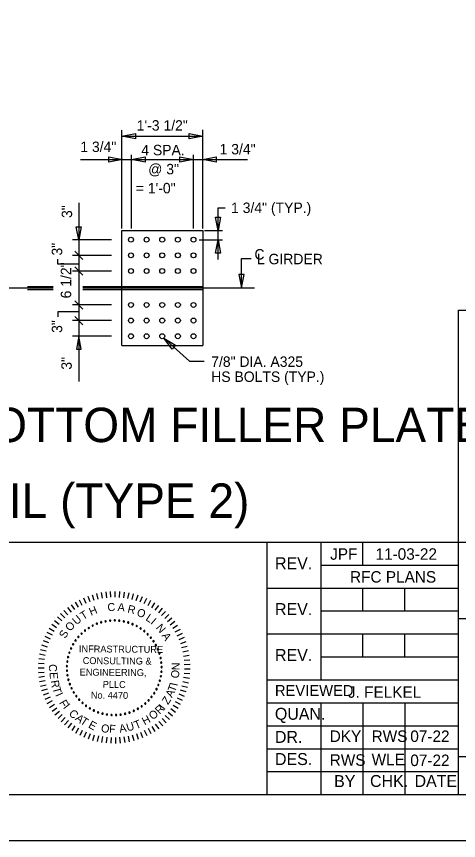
# Model space of a CAD drawing. Extents: x 1970675.2 to 1970715, y 796143 to 796167.2.
# Drawn here: x 1970703.03 to 1970708.33, y 796143.05 to 796152.92 of the extents above; entities that cross this region are included whole.
import ezdxf

# ---------------------------------------------------------------- set-up
doc = ezdxf.new("R2010")
doc.units = 0
for name, color, linetype in [('BR_AUTO DIMENSION', 7, 'Continuous'), ('BR_BORDER LINES', 7, 'Continuous'), ('BR_CENTER LINES', 7, 'Continuous'), ('BR_STRUCTURAL STEEL', 7, 'Continuous'), ('BR_TEXT', 7, 'Continuous'), ('Level 31', 7, 'Continuous')]:
    doc.layers.add(name, color=color, linetype=linetype)

msp = doc.modelspace()

# ---------------------------------------------------------------- linework, layer by layer
at = {"layer": 'BR_AUTO DIMENSION'}
for p, q in [((1970704.2931, 796150.3805), (1970704.2931, 796151.5573)), ((1970705.2619, 796150.3805), (1970705.2619, 796151.5617)), ((1970704.2931, 796151.4842), (1970705.2619, 796151.4842)), ((1970704.4103, 796150.3805), (1970704.4103, 796151.2604)), ((1970705.1525, 796150.3805), (1970705.1525, 796151.2604)), ((1970703.7969, 796151.2042), (1970705.7973, 796151.2042)), ((1970703.7781, 796150.686), (1970703.7781, 796148.5449)), ((1970705.4457, 796150.0076), (1970705.4457, 796150.6251)), ((1970705.4457, 796150.6251), (1970705.5332, 796150.6251)), ((1970705.2845, 796150.3537), (1970705.5013, 796150.3537)), ((1970704.171, 796150.2444), (1970703.7024, 796150.2444)), ((1970705.2194, 796150.2444), (1970705.5013, 796150.2444)), ((1970703.8279, 796150.0063), (1970703.7284, 796150.1074)), ((1970704.171, 796150.0569), (1970703.7024, 796150.0569)), ((1970705.7275, 796150.0186), (1970705.8434, 796150.0186)), ((1970705.7275, 796149.6662), (1970705.7275, 796150.0186)), ((1970704.171, 796149.8694), (1970703.7024, 796149.8694)), ((1970703.8279, 796149.8188), (1970703.7284, 796149.9199)), ((1970703.8279, 796149.4126), (1970703.7284, 796149.5137)), ((1970704.171, 796149.4631), (1970703.7024, 796149.4631)), ((1970704.171, 796149.2756), (1970703.7024, 796149.2756)), ((1970703.8279, 796149.2251), (1970703.7284, 796149.3262)), ((1970704.171, 796149.0881), (1970703.7024, 796149.0881)), ((1970705.1039, 796148.7898), (1970704.7961, 796149.0655)), ((1970705.1039, 796148.7898), (1970705.2808, 796148.7898))]:
    msp.add_line(p, q, dxfattribs=at)
for points in [[(1970704.4556, 796151.453), (1970704.2931, 796151.4842), (1970704.4556, 796151.5155)], [(1970705.0994, 796151.5155), (1970705.2619, 796151.4842), (1970705.0994, 796151.453)], [(1970704.1384, 796151.2354), (1970704.3009, 796151.2042), (1970704.1384, 796151.1729)], [(1970704.5728, 796151.1729), (1970704.4103, 796151.2042), (1970704.5728, 796151.2354)], [(1970704.99, 796151.2354), (1970705.1525, 796151.2042), (1970704.99, 796151.1729)], [(1970705.4244, 796151.1729), (1970705.2619, 796151.2042), (1970705.4244, 796151.2354)], [(1970705.4769, 796150.5162), (1970705.4457, 796150.3537), (1970705.4144, 796150.5162)], [(1970703.8081, 796150.4004), (1970703.7781, 796150.2444), (1970703.7481, 796150.4004)], [(1970705.4144, 796150.0819), (1970705.4457, 796150.2444), (1970705.4769, 796150.0819)], [(1970705.6962, 796149.8287), (1970705.7275, 796149.6662), (1970705.7587, 796149.8287)], [(1970703.7521, 796148.9318), (1970703.8042, 796148.9318), (1970703.7781, 796149.0881)], [(1970704.8963, 796148.9338), (1970704.7961, 796149.0655), (1970704.938, 796148.9803)]]:
    msp.add_lwpolyline(points, close=True, dxfattribs=at)
for points in [[(1970703.7781, 796149.9508), (1970703.5252, 796149.9508), (1970703.5252, 796150.0121)], [(1970703.7781, 796149.3816), (1970703.5252, 796149.3816), (1970703.5252, 796149.3204)]]:
    msp.add_lwpolyline(points, dxfattribs=at)
at = {"layer": 'BR_BORDER LINES'}
for p, q in [((1970708.3272, 796143.5963), (1970708.3272, 796149.4005)), ((1970708.3272, 796149.4005), (1970714.2857, 796149.4005)), ((1970700.1337, 796146.6214), (1970706.0354, 796146.6214)), ((1970706.0354, 796143.5963), (1970706.0354, 796146.6214)), ((1970706.0354, 796146.6214), (1970714.2857, 796146.6214)), ((1970706.6771, 796146.6214), (1970706.6771, 796144.9713)), ((1970707.1813, 796146.3464), (1970707.1813, 796146.6214)), ((1970706.6771, 796146.3464), (1970708.3272, 796146.3464)), ((1970706.0354, 796146.0714), (1970708.3272, 796146.0714)), ((1970707.1813, 796145.7964), (1970707.1813, 796146.0714)), ((1970707.6855, 796145.7964), (1970707.6855, 796146.0714)), ((1970706.6771, 796145.7964), (1970708.3272, 796145.7964)), ((1970708.3272, 796145.7047), (1970708.3272, 796145.7047)), ((1970708.3272, 796145.7047), (1970714.286, 796145.7047)), ((1970706.0354, 796145.5214), (1970708.3272, 796145.5214)), ((1970707.1813, 796145.2463), (1970707.1813, 796145.5214)), ((1970707.6855, 796145.2463), (1970707.6855, 796145.5214)), ((1970706.6771, 796145.2463), (1970708.3272, 796145.2463)), ((1970706.0354, 796144.9713), (1970708.3272, 796144.9713)), ((1970706.0354, 796144.6963), (1970708.3272, 796144.6963)), ((1970706.6771, 796144.6963), (1970706.6771, 796143.5963)), ((1970707.1813, 796144.6963), (1970707.1813, 796143.5963)), ((1970707.6855, 796144.6963), (1970707.6855, 796143.5963)), ((1970706.0354, 796144.4213), (1970708.3272, 796144.4213)), ((1970706.0354, 796144.1463), (1970708.3272, 796144.1463)), ((1970708.3272, 796144.0546), (1970714.2857, 796144.0546)), ((1970706.0354, 796143.8713), (1970708.3272, 796143.8713)), ((1970677.2531, 796143.5963), (1970714.2857, 796143.5963))]:
    msp.add_line(p, q, dxfattribs=at)
at = {"layer": 'BR_CENTER LINES'}
for p, q in [((1970702.8268, 796149.6662), (1970703.471, 796149.6662)), ((1970703.8264, 796149.6662), (1970705.8847, 796149.6662))]:
    msp.add_line(p, q, dxfattribs=at)
at = {"layer": 'BR_STRUCTURAL STEEL'}
for p, q in [((1970704.2931, 796148.9787), (1970704.2931, 796150.3537)), ((1970704.2931, 796150.3537), (1970705.2619, 796150.3537)), ((1970705.2619, 796150.3537), (1970705.2619, 796148.9787)), ((1970703.1614, 796149.6858), (1970703.471, 796149.6858)), ((1970703.8264, 796149.6858), (1970705.2619, 796149.6858)), ((1970703.1614, 796149.6467), (1970703.471, 796149.6467)), ((1970703.8264, 796149.6467), (1970705.2619, 796149.6467)), ((1970704.2931, 796148.9787), (1970705.2619, 796148.9787))]:
    msp.add_line(p, q, dxfattribs=at)
for centre in [(1970704.4025, 796150.2444), (1970704.4025, 796150.2444), (1970704.59, 796150.2444), (1970704.59, 796150.2444), (1970704.7775, 796150.2444), (1970704.7775, 796150.2444), (1970704.965, 796150.2444), (1970704.965, 796150.2444), (1970705.1525, 796150.2444), (1970705.1525, 796150.2444), (1970704.4025, 796150.0569), (1970704.4025, 796150.0569), (1970704.59, 796150.0569), (1970704.59, 796150.0569), (1970704.7775, 796150.0569), (1970704.7775, 796150.0569), (1970704.965, 796150.0569), (1970704.965, 796150.0569), (1970705.1525, 796150.0569), (1970705.1525, 796150.0569), (1970704.4025, 796149.8694), (1970704.4025, 796149.8694), (1970704.59, 796149.8694), (1970704.59, 796149.8694), (1970704.7775, 796149.8694), (1970704.7775, 796149.8694), (1970704.965, 796149.8694), (1970704.965, 796149.8694), (1970705.1525, 796149.8694), (1970705.1525, 796149.8694), (1970704.4025, 796149.4631), (1970704.4025, 796149.4631), (1970704.59, 796149.4631), (1970704.59, 796149.4631), (1970704.7775, 796149.4631), (1970704.7775, 796149.4631), (1970704.965, 796149.4631), (1970704.965, 796149.4631), (1970705.1525, 796149.4631), (1970705.1525, 796149.4631), (1970704.4025, 796149.2756), (1970704.4025, 796149.2756), (1970704.59, 796149.2756), (1970704.59, 796149.2756), (1970704.7775, 796149.2756), (1970704.7775, 796149.2756), (1970704.965, 796149.2756), (1970704.965, 796149.2756), (1970705.1525, 796149.2756), (1970705.1525, 796149.2756), (1970704.4025, 796149.0881), (1970704.4025, 796149.0881), (1970704.59, 796149.0881), (1970704.59, 796149.0881), (1970704.7775, 796149.0881), (1970704.7775, 796149.0881), (1970704.965, 796149.0881), (1970704.965, 796149.0881), (1970705.1525, 796149.0881), (1970705.1525, 796149.0881)]:
    msp.add_circle(centre, 0.0293, dxfattribs=at)
at = {"layer": 'BR_TEXT'}
for p, q in [((1970704.0452, 796146.0174), (1970704.0573, 796145.9485)), ((1970704.1001, 796146.0253), (1970704.1081, 796145.9558)), ((1970704.1555, 796146.0299), (1970704.1592, 796145.96)), ((1970704.211, 796146.0311), (1970704.2104, 796145.961)), ((1970704.2665, 796146.0288), (1970704.2616, 796145.959)), ((1970704.3217, 796146.0232), (1970704.3126, 796145.9538)), ((1970703.7831, 796145.9288), (1970703.8154, 796145.8667)), ((1970703.8331, 796145.9529), (1970703.8616, 796145.8889)), ((1970703.8846, 796145.9738), (1970703.9091, 796145.9082)), ((1970703.9372, 796145.9916), (1970703.9577, 796145.9247)), ((1970703.9908, 796146.0062), (1970704.0071, 796145.9381)), ((1970704.3765, 796146.0143), (1970704.3632, 796145.9455)), ((1970704.4307, 796146.002), (1970704.4132, 796145.9342)), ((1970704.484, 796145.9864), (1970704.4624, 796145.9198)), ((1970704.5363, 796145.9677), (1970704.5106, 796145.9025)), ((1970704.5873, 796145.9457), (1970704.5577, 796145.8822)), ((1970704.6369, 796145.9207), (1970704.6035, 796145.8591)), ((1970703.643, 796145.839), (1970703.6861, 796145.7838)), ((1970703.6879, 796145.8718), (1970703.7275, 796145.8141)), ((1970703.7346, 796145.9018), (1970703.7707, 796145.8417)), ((1970704.6848, 796145.8928), (1970704.6478, 796145.8333)), ((1970704.731, 796145.8619), (1970704.6904, 796145.8048)), ((1970704.7752, 796145.8283), (1970704.7312, 796145.7738)), ((1970703.5216, 796145.7252), (1970703.574, 796145.6788)), ((1970703.5597, 796145.7656), (1970703.6092, 796145.7161)), ((1970703.6003, 796145.8036), (1970703.6466, 796145.7511)), ((1970704.8173, 796145.7921), (1970704.77, 796145.7404)), ((1970704.8571, 796145.7533), (1970704.8068, 796145.7046)), ((1970703.4531, 796145.6379), (1970703.5108, 796145.5982)), ((1970703.486, 796145.6826), (1970703.5412, 796145.6395)), ((1970704.8944, 796145.7122), (1970704.8412, 796145.6667)), ((1970704.9292, 796145.6689), (1970704.8733, 796145.6267)), ((1970704.9613, 796145.6236), (1970704.903, 796145.5848)), ((1970703.3957, 796145.5429), (1970703.4578, 796145.5105)), ((1970703.423, 796145.5913), (1970703.4829, 796145.5551)), ((1970704.9905, 796145.5764), (1970704.9299, 796145.5413)), ((1970705.0169, 796145.5275), (1970704.9542, 796145.4961)), ((1970703.3503, 796145.4416), (1970703.4159, 796145.417)), ((1970703.3715, 796145.4929), (1970703.4354, 796145.4644)), ((1970705.0401, 796145.4771), (1970704.9757, 796145.4496)), ((1970705.0603, 796145.4254), (1970704.9944, 796145.4018)), ((1970703.3176, 796145.3355), (1970703.3857, 796145.319)), ((1970703.3323, 796145.389), (1970703.3993, 796145.3685)), ((1970705.0773, 796145.3725), (1970705.01, 796145.353)), ((1970703.298, 796145.2262), (1970703.3676, 796145.2182)), ((1970703.3061, 796145.2811), (1970703.3751, 796145.2689)), ((1970705.091, 796145.3187), (1970705.0227, 796145.3034)), ((1970705.1014, 796145.2641), (1970705.0323, 796145.253)), ((1970703.2933, 796145.1709), (1970703.3632, 796145.1671)), ((1970705.1085, 796145.209), (1970705.0388, 796145.2022)), ((1970705.1122, 796145.1536), (1970705.0422, 796145.151)), ((1970703.2919, 796145.1154), (1970703.3619, 796145.1159)), ((1970703.2939, 796145.0599), (1970703.3638, 796145.0646)), ((1970705.1095, 796145.0427), (1970705.0397, 796145.0486)), ((1970705.1126, 796145.0981), (1970705.0425, 796145.0998)), ((1970703.2993, 796145.0046), (1970703.3688, 796145.0136)), ((1970703.3081, 796144.9498), (1970703.3768, 796144.963)), ((1970705.0933, 796144.9328), (1970705.0247, 796144.9472)), ((1970705.103, 796144.9875), (1970705.0337, 796144.9977)), ((1970703.3201, 796144.8956), (1970703.388, 796144.913)), ((1970703.3355, 796144.8422), (1970703.4021, 796144.8637)), ((1970705.0638, 796144.8258), (1970704.9975, 796144.8484)), ((1970705.0801, 796144.8789), (1970705.0126, 796144.8974)), ((1970703.3541, 796144.7899), (1970703.4193, 796144.8154)), ((1970703.3758, 796144.7388), (1970703.4394, 796144.7682)), ((1970705.0215, 796144.7232), (1970704.9584, 796144.7537)), ((1970705.0442, 796144.7738), (1970704.9794, 796144.8004)), ((1970703.4006, 796144.6891), (1970703.4623, 796144.7224)), ((1970703.4284, 796144.641), (1970703.4879, 796144.678)), ((1970703.4591, 796144.5947), (1970703.5162, 796144.6353)), ((1970704.967, 796144.6264), (1970704.9082, 796144.6644)), ((1970704.9957, 796144.674), (1970704.9347, 796144.7083)), ((1970703.4926, 796144.5504), (1970703.5471, 796144.5943)), ((1970703.5286, 796144.5082), (1970703.5804, 796144.5554)), ((1970704.8643, 796144.4955), (1970704.8134, 796144.5435)), ((1970704.9012, 796144.537), (1970704.8474, 796144.5819)), ((1970704.9355, 796144.5807), (1970704.879, 796144.6222)), ((1970703.5672, 796144.4683), (1970703.616, 796144.5185)), ((1970703.6082, 796144.4307), (1970703.6538, 796144.4839)), ((1970703.6513, 796144.3958), (1970703.6937, 796144.4516)), ((1970704.7395, 796144.3855), (1970704.6981, 796144.442)), ((1970704.7833, 796144.4196), (1970704.7386, 796144.4735)), ((1970704.825, 796144.4563), (1970704.777, 796144.5074)), ((1970703.6966, 796144.3636), (1970703.7354, 796144.4218)), ((1970703.7437, 796144.3341), (1970703.7789, 796144.3947)), ((1970703.7925, 796144.3076), (1970703.8239, 796144.3702)), ((1970703.8428, 796144.2842), (1970703.8704, 796144.3485)), ((1970704.546, 796144.2775), (1970704.5195, 796144.3423)), ((1970704.5968, 796144.3), (1970704.5663, 796144.3631)), ((1970704.6461, 796144.3256), (1970704.6119, 796144.3867)), ((1970704.6937, 796144.3541), (1970704.6558, 796144.413)), ((1970703.8944, 796144.2638), (1970703.918, 796144.3297)), ((1970703.9473, 796144.2466), (1970703.9668, 796144.3139)), ((1970704.001, 796144.2327), (1970704.0164, 796144.301)), ((1970704.0555, 796144.2221), (1970704.0667, 796144.2912)), ((1970704.1106, 796144.2148), (1970704.1175, 796144.2845)), ((1970704.166, 796144.2109), (1970704.1687, 796144.2809)), ((1970704.2215, 796144.2103), (1970704.2199, 796144.2804)), ((1970704.2769, 796144.2132), (1970704.2711, 796144.283)), ((1970704.3321, 796144.2194), (1970704.3221, 796144.2888)), ((1970704.3868, 796144.229), (1970704.3726, 796144.2976)), ((1970704.4408, 796144.2419), (1970704.4224, 796144.3095)), ((1970704.494, 796144.2581), (1970704.4715, 796144.3244))]:
    msp.add_line(p, q, dxfattribs=at)
for centre, start, end in [((1970703.944, 796145.621), 27.21914, 207.21914), ((1970703.944, 796145.621), 207.21914, 27.21914), ((1970703.994, 796145.6436), 21.68068, 201.68068), ((1970703.994, 796145.6436), 201.68068, 21.68068), ((1970704.0459, 796145.6613), 16.14222, 196.14222), ((1970704.0459, 796145.6613), 196.14222, 16.14222), ((1970704.0992, 796145.6738), 10.60376, 190.60376), ((1970704.0992, 796145.6738), 190.60376, 10.60376), ((1970704.1535, 796145.6812), 5.06529, 185.06529), ((1970704.1535, 796145.6812), 185.06529, 5.06529), ((1970704.2083, 796145.6833), 359.52683, 179.52683), ((1970704.2083, 796145.6833), 179.52683, 359.52683), ((1970704.263, 796145.6801), 173.98837, 353.98837), ((1970704.263, 796145.6801), 353.98837, 173.98837), ((1970704.3172, 796145.6716), 168.44991, 348.44991), ((1970704.3172, 796145.6716), 348.44991, 168.44991), ((1970704.3703, 796145.6579), 162.91145, 342.91145), ((1970704.3703, 796145.6579), 342.91145, 162.91145), ((1970704.4218, 796145.6392), 157.37299, 337.37299), ((1970704.4218, 796145.6392), 337.37299, 157.37299), ((1970704.4713, 796145.6156), 331.83453, 151.83453), ((1970703.8104, 796145.526), 43.83453, 223.83453), ((1970703.8104, 796145.526), 223.83453, 43.83453), ((1970703.8518, 796145.562), 38.29606, 218.29606), ((1970703.8518, 796145.562), 218.29606, 38.29606), ((1970703.8965, 796145.5937), 32.7576, 212.7576), ((1970703.8965, 796145.5937), 212.7576, 32.7576), ((1970704.4713, 796145.6156), 151.83453, 331.83453), ((1970704.5182, 796145.5873), 146.29606, 326.29606), ((1970704.5182, 796145.5873), 326.29606, 146.29606), ((1970704.5622, 796145.5547), 140.7576, 320.7576), ((1970704.5622, 796145.5547), 320.7576, 140.7576), ((1970704.6029, 796145.5179), 135.21914, 315.21914), ((1970704.6029, 796145.5179), 315.21914, 135.21914), ((1970703.739, 796145.4431), 54.91145, 234.91145), ((1970703.739, 796145.4431), 234.91145, 54.91145), ((1970703.7727, 796145.4863), 49.37299, 229.37299), ((1970703.7727, 796145.4863), 229.37299, 49.37299), ((1970704.6398, 796145.4774), 129.68068, 309.68068), ((1970704.6398, 796145.4774), 309.68068, 129.68068), ((1970704.6726, 796145.4335), 124.14222, 304.14222), ((1970704.6726, 796145.4335), 304.14222, 124.14222), ((1970703.6848, 796145.3479), 65.98837, 245.98837), ((1970703.6848, 796145.3479), 245.98837, 65.98837), ((1970703.7096, 796145.3968), 60.44991, 240.44991), ((1970703.7096, 796145.3968), 240.44991, 60.44991), ((1970704.7011, 796145.3866), 118.60376, 298.60376), ((1970704.7011, 796145.3866), 298.60376, 118.60376), ((1970704.7249, 796145.3373), 113.06529, 293.06529), ((1970704.7249, 796145.3373), 293.06529, 113.06529), ((1970703.6499, 796145.2441), 77.06529, 257.06529), ((1970703.6499, 796145.2441), 257.06529, 77.06529), ((1970703.6648, 796145.2969), 71.52683, 251.52683), ((1970703.6648, 796145.2969), 251.52683, 71.52683), ((1970704.7438, 796145.2858), 107.52683, 287.52683), ((1970704.7438, 796145.2858), 287.52683, 107.52683), ((1970704.7576, 796145.2328), 101.98837, 281.98837), ((1970704.7576, 796145.2328), 281.98837, 101.98837), ((1970703.6356, 796145.1356), 88.14222, 268.14222), ((1970703.6401, 796145.1902), 82.60376, 262.60376), ((1970703.6356, 796145.1356), 268.14222, 88.14222), ((1970703.6401, 796145.1902), 262.60376, 82.60376), ((1970704.7663, 796145.1787), 96.44991, 276.44991), ((1970704.7697, 796145.1239), 90.91145, 270.91145), ((1970704.7663, 796145.1787), 276.44991, 96.44991), ((1970704.7697, 796145.1239), 270.91145, 90.91145), ((1970703.6363, 796145.0808), 93.68068, 273.68068), ((1970703.6424, 796145.0263), 99.21914, 279.21914), ((1970703.6363, 796145.0808), 273.68068, 93.68068), ((1970703.6424, 796145.0263), 279.21914, 99.21914), ((1970704.7678, 796145.0692), 85.37299, 265.37299), ((1970704.7678, 796145.0692), 265.37299, 85.37299), ((1970703.6537, 796144.9726), 104.7576, 284.7576), ((1970703.6537, 796144.9726), 284.7576, 104.7576), ((1970704.7483, 796144.9614), 74.29606, 254.29606), ((1970704.7483, 796144.9614), 254.29606, 74.29606), ((1970704.7607, 796145.0148), 79.83453, 259.83453), ((1970704.7607, 796145.0148), 259.83453, 79.83453), ((1970703.6701, 796144.9203), 110.29606, 290.29606), ((1970703.6701, 796144.9203), 290.29606, 110.29606), ((1970703.6914, 796144.8699), 115.83453, 295.83453), ((1970703.6914, 796144.8699), 295.83453, 115.83453), ((1970704.7084, 796144.8594), 63.21914, 243.21914), ((1970704.7084, 796144.8594), 243.21914, 63.21914), ((1970704.7308, 796144.9095), 68.7576, 248.7576), ((1970704.7308, 796144.9095), 248.7576, 68.7576), ((1970703.7176, 796144.8217), 121.37299, 301.37299), ((1970703.7176, 796144.8217), 301.37299, 121.37299), ((1970703.7483, 796144.7763), 126.91145, 306.91145), ((1970703.7483, 796144.7763), 306.91145, 126.91145), ((1970703.7832, 796144.734), 132.44991, 312.44991), ((1970703.7832, 796144.734), 312.44991, 132.44991), ((1970704.6139, 796144.7255), 46.60376, 226.60376), ((1970704.6497, 796144.767), 52.14222, 232.14222), ((1970704.6497, 796144.767), 232.14222, 52.14222), ((1970704.6813, 796144.8118), 57.68068, 237.68068), ((1970704.6813, 796144.8118), 237.68068, 57.68068), ((1970703.822, 796144.6953), 137.98837, 317.98837), ((1970703.822, 796144.6953), 317.98837, 137.98837), ((1970703.8644, 796144.6606), 143.52683, 323.52683), ((1970703.8644, 796144.6606), 323.52683, 143.52683), ((1970703.9099, 796144.63), 149.06529, 329.06529), ((1970703.9099, 796144.63), 329.06529, 149.06529), ((1970704.5312, 796144.6537), 35.52683, 215.52683), ((1970704.5312, 796144.6537), 215.52683, 35.52683), ((1970704.5743, 796144.6876), 41.06529, 221.06529), ((1970704.5743, 796144.6876), 221.06529, 41.06529), ((1970704.6139, 796144.7255), 226.60376, 46.60376), ((1970703.9582, 796144.6041), 154.60376, 334.60376), ((1970703.9582, 796144.6041), 334.60376, 154.60376), ((1970704.0087, 796144.5829), 160.14222, 340.14222), ((1970704.0087, 796144.5829), 340.14222, 160.14222), ((1970704.0611, 796144.5667), 165.68068, 345.68068), ((1970704.0611, 796144.5667), 345.68068, 165.68068), ((1970704.1148, 796144.5556), 171.21914, 351.21914), ((1970704.1148, 796144.5556), 351.21914, 171.21914), ((1970704.1693, 796144.5497), 356.7576, 176.7576), ((1970704.1693, 796144.5497), 176.7576, 356.7576), ((1970704.2241, 796144.5492), 2.29606, 182.29606), ((1970704.2241, 796144.5492), 182.29606, 2.29606), ((1970704.2787, 796144.5539), 7.83453, 187.83453), ((1970704.2787, 796144.5539), 187.83453, 7.83453), ((1970704.3326, 796144.5639), 13.37299, 193.37299), ((1970704.3326, 796144.5639), 193.37299, 13.37299), ((1970704.3853, 796144.579), 18.91145, 198.91145), ((1970704.3853, 796144.579), 198.91145, 18.91145), ((1970704.4363, 796144.5992), 24.44991, 204.44991), ((1970704.4363, 796144.5992), 204.44991, 24.44991), ((1970704.4851, 796144.6242), 29.98837, 209.98837), ((1970704.4851, 796144.6242), 209.98837, 29.98837)]:
    msp.add_arc(centre, 0.00771, start, end, dxfattribs=at)
at = {"layer": 'Level 31'}
msp.add_lwpolyline([(1970675.2365, 796167.2463), (1970675.2365, 796143.0464), (1970714.8364, 796143.0464), (1970714.8364, 796167.2463)], dxfattribs=at)

# ---------------------------------------------------------------- texts
at = {"layer": 'BR_TEXT'}
for s, height, p in [('1\'-3 1/2"', 0.125, (1970704.472, 796151.5513)), ('1 3/4"', 0.125, (1970703.7961, 796151.2951)), ('4 SPA. ', 0.125, (1970704.5265, 796151.2561)), ('1 3/4"', 0.125, (1970705.4648, 796151.2666)), ('@ 3" ', 0.125, (1970704.6096, 796151.028)), ('= 1\'-0"', 0.125, (1970704.4607, 796150.7999)), ('1 3/4" (TYP.)', 0.125, (1970705.6023, 796150.5648)), ('C', 0.125, (1970705.8822, 796150.0068)), ('L GIRDER', 0.125, (1970705.9117, 796149.9503)), ('7/8" DIA. A325', 0.125, (1970705.3643, 796148.7208)), ('HS BOLTS (TYP.)', 0.125, (1970705.3643, 796148.5406)), ('BOTTOM FILLER PLATE', 0.4125, (1970702.3607, 796147.8194)), ('FIELD SPLICE DETAIL (TYPE 2)', 0.4125, (1970697.6374, 796146.912)), ('JPF', 0.13749, (1970706.7894, 796146.4101)), ('11-03-22', 0.13749, (1970707.3329, 796146.4101)), ('REV.', 0.14301, (1970706.1286, 796146.2973)), ('RFC PLANS', 0.13749, (1970707.0275, 796146.1362)), ('REV.', 0.14301, (1970706.1286, 796145.7473)), ('REV.', 0.14301, (1970706.1286, 796145.1973)), ('REVIEWED', 0.13201, (1970706.1278, 796144.7772)), ('J. FELKEL', 0.13749, (1970707.0023, 796144.7562)), ('QUAN.', 0.14301, (1970706.1272, 796144.493)), ('DR.', 0.14301, (1970706.1274, 796144.2163)), ('DKY', 0.13749, (1970706.7841, 796144.2273)), ('RWS', 0.13749, (1970707.2861, 796144.2273)), ('07-22', 0.13749, (1970707.7496, 796144.2273)), ('DES.', 0.14301, (1970706.1285, 796143.9509)), ('RWS', 0.13749, (1970706.7841, 796143.942)), ('WLE', 0.13749, (1970707.2865, 796143.948)), ('07-22', 0.13749, (1970707.7496, 796143.9384)), ('BY', 0.14301, (1970706.837, 796143.6865)), ('CHK.', 0.14301, (1970707.2669, 796143.688)), ('DATE', 0.14301, (1970707.8006, 796143.6881))]:
    msp.add_text(s, height=height, dxfattribs=at).set_placement(p)
for s, height, rotation, p in [('3"', 0.125, 90, (1970703.6978, 796150.5049)), ('3"', 0.125, 90, (1970703.5793, 796150.0547)), ('6 1/2"', 0.125, 90, (1970703.6867, 796149.5415)), ('3"', 0.125, 90, (1970703.5793, 796149.1279)), ('3"', 0.125, 90, (1970703.6937, 796148.6875)), ('H', 0.0959, 22.78817, (1970703.9241, 796145.7374)), ('C', 0.0959, 4.72812, (1970704.1252, 796145.7917)), ('A', 0.0959, 355.69809, (1970704.2402, 796145.7971)), ('R', 0.0959, 346.66807, (1970704.3549, 796145.7785)), ('O', 0.0959, 337.63804, (1970704.4624, 796145.7457)), ('U', 0.0959, 40.84822, (1970703.7502, 796145.6232)), ('T', 0.0959, 31.81819, (1970703.8308, 796145.6849)), ('L', 0.0959, 327.10802, (1970704.5711, 796145.6902)), ('O', 0.0959, 49.87824, (1970703.6765, 796145.5451)), ('I', 0.0959, 319.578, (1970704.6289, 796145.6486)), ('N', 0.0959, 310.54797, (1970704.6958, 796145.5927)), ('S', 0.0959, 58.90827, (1970703.6155, 796145.4591)), ('A', 0.0959, 301.51795, (1970704.7674, 796145.5021)), ('INFRASTRUCTURE', 0.082248, 359.52683, (1970703.779, 796145.3023)), ('CONSULTING &', 0.082248, 359.52683, (1970703.8244, 796145.1609)), ('C', 0.0959, 267.02504, (1970703.423, 796145.1622)), ('N', 0.0959, 89.20849, (1970704.9866, 796145.0855)), ('E', 0.0959, 273.02504, (1970703.4279, 796145.0615)), ('ENGINEERING,', 0.082248, 359.52683, (1970703.7875, 796145.0229)), ('O', 0.0959, 83.20849, (1970704.9744, 796144.9849)), ('R', 0.0959, 279.02504, (1970703.4419, 796144.9599)), ('PLLC', 0.08225, 359.52683, (1970704.0644, 796144.876)), ('I', 0.0959, 77.90926, (1970704.9574, 796144.8921)), ('T', 0.0959, 285.02504, (1970703.4611, 796144.8733)), ('A', 0.0959, 63.39539, (1970704.8952, 796144.7515)), ('T', 0.0959, 69.39539, (1970704.9291, 796144.8179)), ('I', 0.0959, 293.77127, (1970703.4937, 796144.7929)), ('F', 0.0959, 299.77127, (1970703.539, 796144.6982)), ('No. 4470', 0.08225, 359.52683, (1970703.9219, 796144.7474)), ('Z', 0.0959, 57.39539, (1970704.847, 796144.6675)), ('I', 0.0959, 308.52683, (1970703.5853, 796144.639)), ('R', 0.0959, 44.52683, (1970704.7475, 796144.5521)), ('I', 0.0959, 52.33388, (1970704.8018, 796144.6041)), ('C', 0.0959, 314.52683, (1970703.6506, 796144.5618)), ('A', 0.0959, 320.52683, (1970703.7267, 796144.4974)), ('H', 0.0959, 28.52683, (1970704.5663, 796144.4245)), ('O', 0.0959, 38.52683, (1970704.6633, 796144.4861)), ('T', 0.0959, 326.52683, (1970703.7866, 796144.4551)), ('E', 0.0959, 332.52683, (1970703.884, 796144.4025)), ('O', 0.0959, 350.52683, (1970704.0382, 796144.3488)), ('A', 0.0959, 10.52683, (1970704.2706, 796144.3369)), ('U', 0.0959, 16.52683, (1970704.3629, 796144.3518)), ('T', 0.0959, 22.52683, (1970704.4639, 796144.3786)), ('F', 0.0959, 356.52683, (1970704.1388, 796144.3387))]:
    msp.add_text(s, height=height, rotation=rotation, dxfattribs=at).set_placement(p)

doc.saveas('drawing.dxf')
